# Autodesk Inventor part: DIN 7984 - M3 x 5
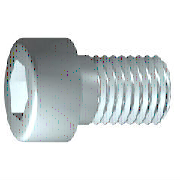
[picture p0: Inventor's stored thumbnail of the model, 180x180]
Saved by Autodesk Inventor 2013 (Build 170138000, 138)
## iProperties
Created: 2012-02
Part Number: DIN 7984 - M3 x 5
Material: Steel, Mild
Description: Cylinder Head Cap Screw
Document SubType Name: Modeling
Standard: DIN 7984
Designer: rYan
Standard Revision: 1985
Standards Organization: DIN
Language: en-US
Size Designation: M3 x 5
Categories: <MemberInstance><Categories><Category DisplayName="Fasteners" InternalName="e4da775c-781d-43d5-af7c-5136215cf5a6" Mnemonic="FSTN"><Category DisplayName="Bolts"
Density: 1 g/cm^3
IsCustomPart: 0
Author: rYan
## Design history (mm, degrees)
sketch "Sketch1"
  geometry: L1 (0.167, 0)-(5, 0); L2 (5, 0)-(5, 1.5); L3 (5, 1.5)-(1.5, 1.5); L4 (1.5, 1.5)-(1.193, 1.5); L5 (1.193, 1.5)-(0, 1.5); L6 (0, 1.5)-(0, 2.75); L7 (0, 2.75)-(-2, 2.75); L8 (-2, 2.75)-(-2, 1.155); L9 (-2, 1.155)-(-0.5, 1.155); L10 (-0.5, 1.155)-(0.167, 0); L11 (-3.4, 0)-(6.4, 0) reference; L12 (0, -0.55)-(0, 3.3) reference; L13 (1.5, 1.5)-(0, 1.5)
  constraints: 22 end point, 6 parallel, 2 collinear, 2 perpendicular, 1 horizontal, 1 point on line
  dimensions: "d1" = 3.5 distance from line of L3.end L2 (= GEL); "d2" = 0.30683 distance of L4.end L3.end (computed from GAL); "d3" = 2 distance between parallel lines of L8 L6 (= KOH); "d4" = 1.5 distance of L8.end L9.end (= INTI); "d5" = 60 deg angle of L10 L1; "d6" = 3 diameter of L3 L1 (= GD); "d7" = 3 diameter of L5 L1 (= BDM); "d8" = 2.3094 diameter of L9 L1 (= 1.1547 x SW); "d9" = 5.5 diameter of L7 L1 (= KOD); "d26" = 5 distance between parallel lines of L12 L2 (= NLG)
revolve "Body" sketch "Sketch1" stored, may be unused: angle "d10" = 90 deg
sketch "Sketch2"
  geometry: L1 (0, -3.85)-(0, 3.85) reference; L2 (-3.85, 0)-(3.85, 0) reference; L3 (1.155, 0)-(0.577, -1); L4 (0.577, -1)-(-0.577, -1); L5 (-0.577, -1)-(-1.155, 0); L6 (-1.155, 0)-(-0.577, 1); L7 (-0.577, 1)-(0.577, 1); L8 (0.577, 1)-(1.155, 0); 2 further points
  constraints: 12 end point, 1 coincident, 1 horizontal alignment, 1 point on line, 12 other
extrude "Slot" join sketch "Sketch2" stored distance "d11" = 10; taper "d12" = 0 deg
workplane "Work Plane1"
fillet "Fillet2" dims "d30" = 0.1 (= R)
body "Solid1"
fillet "Fillet1" dims "d17" = 0.3 (= RR)
feature "Thread" dims "d13" = 3.5 (= GEL), "d14" = 0
chamfer "Chamfer1" distance "d15" = 0.30673 (= -0.5 x SPD + 0.5 x GD); stored, may be unused: second distance "d16" = 0.30673 (= GUL), angle "d27" = 45 deg
other parameters: "GD" = 3 (= NND) [user parameter; used in 2 equation terms], "NLG" = 5 [user parameter; used in 1 equation term], "GEL" = 3.5 [user parameter; used in 2 equation terms], "KOD" = 5.5 [user parameter; used in 1 equation term], "KOH" = 2 [user parameter; used in 1 equation term], "INTI" = 1.5 [user parameter; used in 1 equation term], "GAL" = 0.30673 (= 0.61345 x PTC) [user parameter; used in 1 equation term], "GUL" = 0.30673 (= 0.61345 x PTC) [user parameter; used in 1 equation term], "BDM" = 3 (= NND) [user parameter; used in 1 equation term], "SW" = 2 [user parameter; used in 2 equation terms], "RR" = 0.3 [user parameter; used in 1 equation term], "SPD" = 2.38655 (= NND - 1.2269 x PTC) [user parameter; used in 1 equation term], "d19" = 0, "d28" = 0, "d29" = 0, "R" = 0.1 [user parameter; used in 1 equation term], "TOA" = 30 deg [user parameter], "GD1" = 2.38655 (= THREADDIA - 1.2269 x PTC) [user parameter], "THREADDIA" = 3 [user parameter; used in 1 equation term], "FAWI" = 45 deg [user parameter], "ANG" = 120 deg [user parameter], "PTC" = 0.5 [user parameter; used in 5 equation terms], "NND" = 3 [user parameter; used in 3 equation terms], "E0" = 2.31 (= 1.155 x SW) [user parameter]
